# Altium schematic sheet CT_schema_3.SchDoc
size 362 x 325 mm
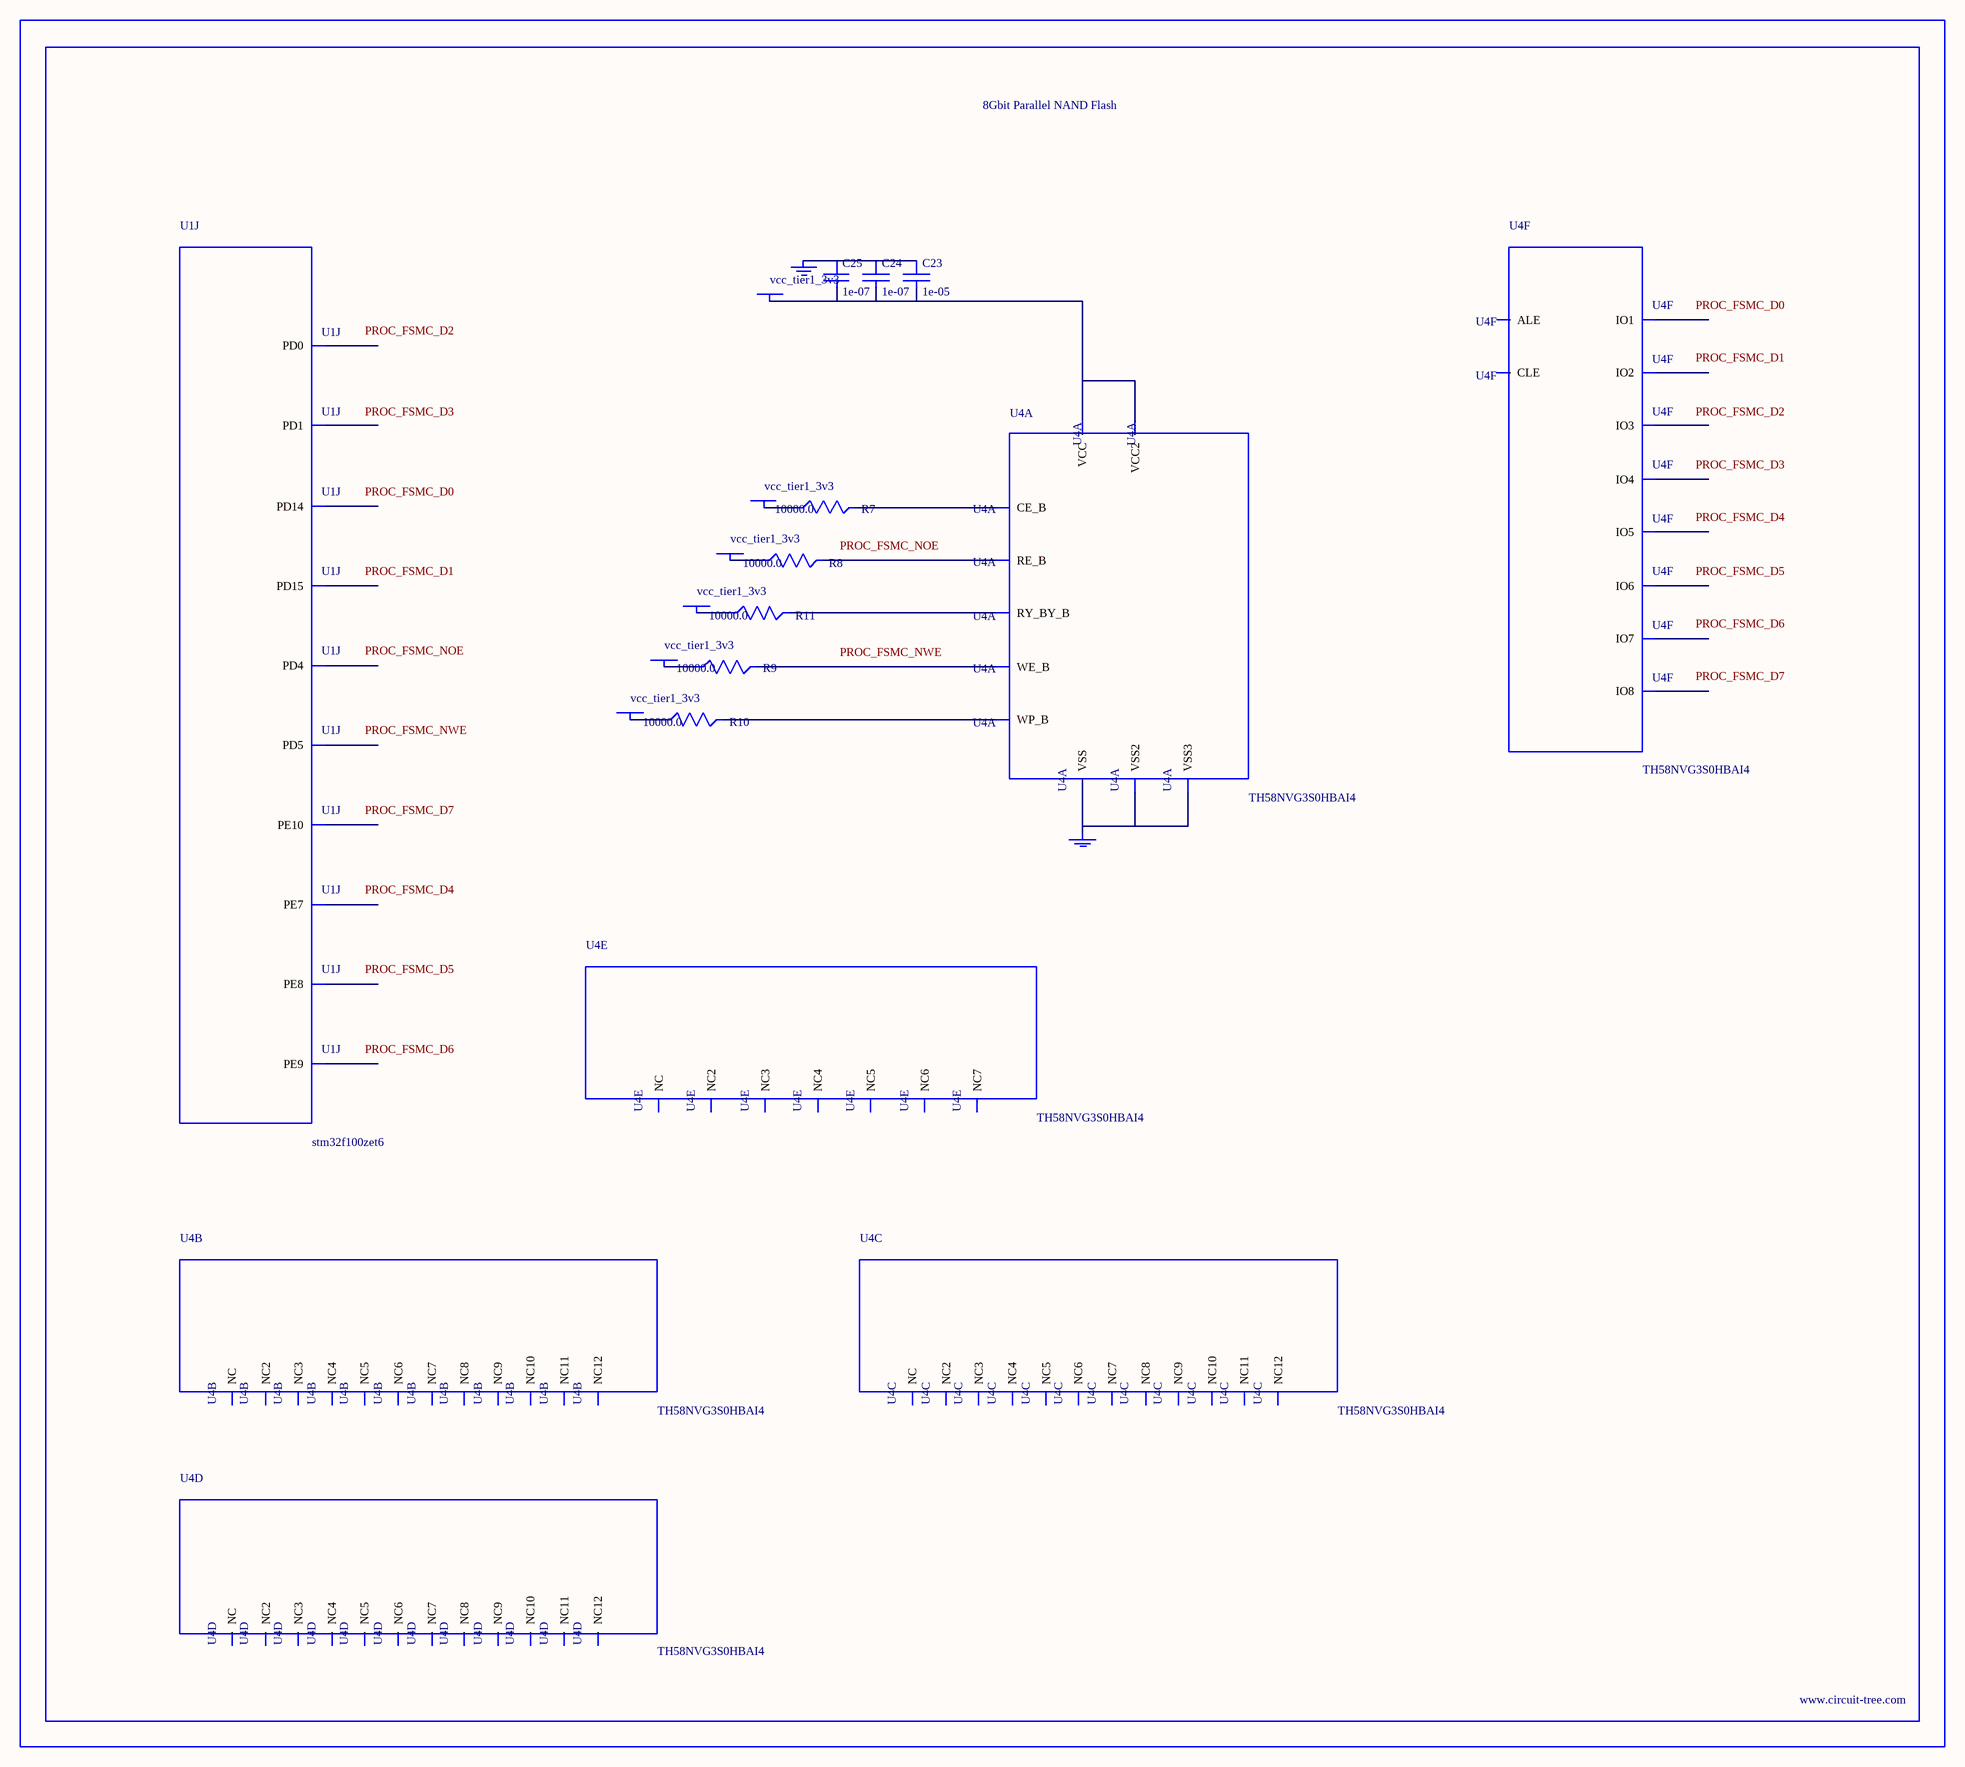
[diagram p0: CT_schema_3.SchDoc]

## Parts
BORDER2  (no value)
C23  1e-05  [C0805]
C24  1e-07  [C0402]
C25  1e-07  [C0402]
GND_INSTANCE_2_0  (no value)
GND_INSTANCE_2_1  (no value)
POWER_INSTANCE_2_0  vcc_tier1_3v3
POWER_INSTANCE_2_1  vcc_tier1_3v3
POWER_INSTANCE_2_2  vcc_tier1_3v3
POWER_INSTANCE_2_3  vcc_tier1_3v3
POWER_INSTANCE_2_4  vcc_tier1_3v3
POWER_INSTANCE_2_5  vcc_tier1_3v3
R7  10000.0  [R0603]
R8  10000.0  [R0603]
R9  10000.0  [R0603]
R10  10000.0  [R0603]
R11  10000.0  [R0603]
U1  stm32f100zet6  [LQFP144]  (part J of 11)
U4  TH58NVG3S0HBAI4  [TH58NVG3S0HBAI4]  (parts A,B,C,D,E,F of 6)

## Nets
NetC23_1: C23.1 C24.1 C25.1 GND_INSTANCE_2_0.0(GND)
NetC23_2: C23.2 C24.2 C25.2 POWER_INSTANCE_2_5.0(PWR) U4.H8(VCC) U4.J6(VCC2)
NetGND_INSTANCE_2_1_0: GND_INSTANCE_2_1.0(GND) U4.C5(VSS) U4.K3(VSS2) U4.K8(VSS3)
NetPOWER_INSTANCE_2_0_0: POWER_INSTANCE_2_0.0(PWR) R7.1
NetPOWER_INSTANCE_2_1_0: POWER_INSTANCE_2_1.0(PWR) R8.1
NetPOWER_INSTANCE_2_2_0: POWER_INSTANCE_2_2.0(PWR) R9.1
NetPOWER_INSTANCE_2_3_0: POWER_INSTANCE_2_3.0(PWR) R10.1
NetPOWER_INSTANCE_2_4_0: POWER_INSTANCE_2_4.0(PWR) R11.1
NetR7_2: R7.2 U4.C6(CE_B)
NetR8_2: R8.2 U4.D4(RE_B)
NetR9_2: R9.2 U4.C7(WE_B)
NetR10_2: R10.2 U4.C3(WP_B)
NetR11_2: R11.2 U4.C8(RY_BY_B)

Not connected (* = marked no-connect by the designer): U1 58(PE7) 59(PE8) 60(PE9) 63(PE10) 85(PD14) 86(PD15) 114(PD0) 115(PD1) 118(PD4) 119(PD5); U4 A1(NC) A2(NC3) A9(NC4) A10(NC2) B1(NC5) B9(NC7) B10(NC6) C4(ALE) D3(NC8) D5(CLE) D6(NC9) D7(NC10) D8(NC11) E3(NC12) E4(NC) E5(NC2) E6(NC3) E7(NC4) E8(NC5) F3(NC6) F4(NC7) F5(NC8) F6(NC9) F7(NC10) F8(NC11) G3(NC12) G4(NC) G5(NC2) G6(NC3) G7(NC4) G8(NC5) H3(NC6) H4(IO1) H5(NC7) H6(NC8) H7(NC9) J3(NC10) J4(IO2) J5(NC11) J7(IO6) J8(IO8) K4(IO3) K5(IO4) K6(IO5) K7(IO7) L1(NC12) L2(NC2) L9(NC3) L10(NC) M1(NC4) M2(NC6) M9(NC7) M10(NC5)

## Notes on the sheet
- Labels drawn without touching a wire or pin: PROC_FSMC_D0, PROC_FSMC_D1, PROC_FSMC_D2, PROC_FSMC_D3, PROC_FSMC_D4, PROC_FSMC_D5, PROC_FSMC_D6, PROC_FSMC_D7, PROC_FSMC_NOE, PROC_FSMC_NWE

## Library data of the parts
BORDER2 = BORDER_PAGE2
C23 = C0805C106K8RACTU
C24 C25 = C0402C104K3RACTU
GND_INSTANCE_2_0 GND_INSTANCE_2_1 = GND
POWER_INSTANCE_2_0-POWER_INSTANCE_2_5 = PWR
R7-R11 = RC0603JR-0710KL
